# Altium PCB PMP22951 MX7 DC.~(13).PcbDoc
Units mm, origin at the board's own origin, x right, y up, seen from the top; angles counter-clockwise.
Board outline 96 x 43 mm, 6 copper layers (Top Layer, Layer 1, Layer 3, Layer 4, Layer 2, Bottom Layer), stack 1.671 mm thick; 4 components, 8 nets, 16 pads, 0 vias.
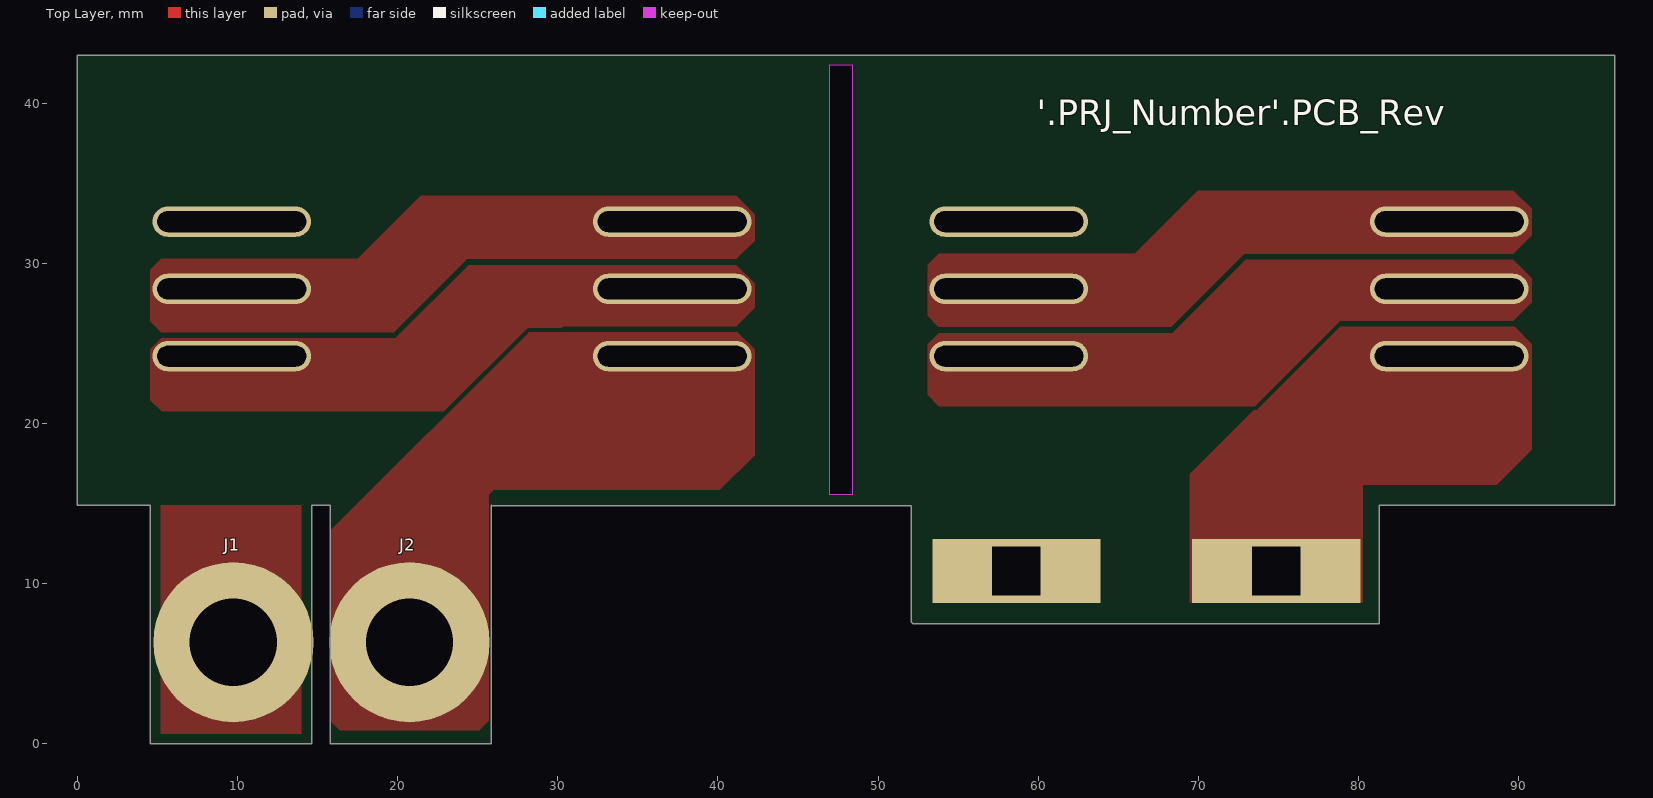
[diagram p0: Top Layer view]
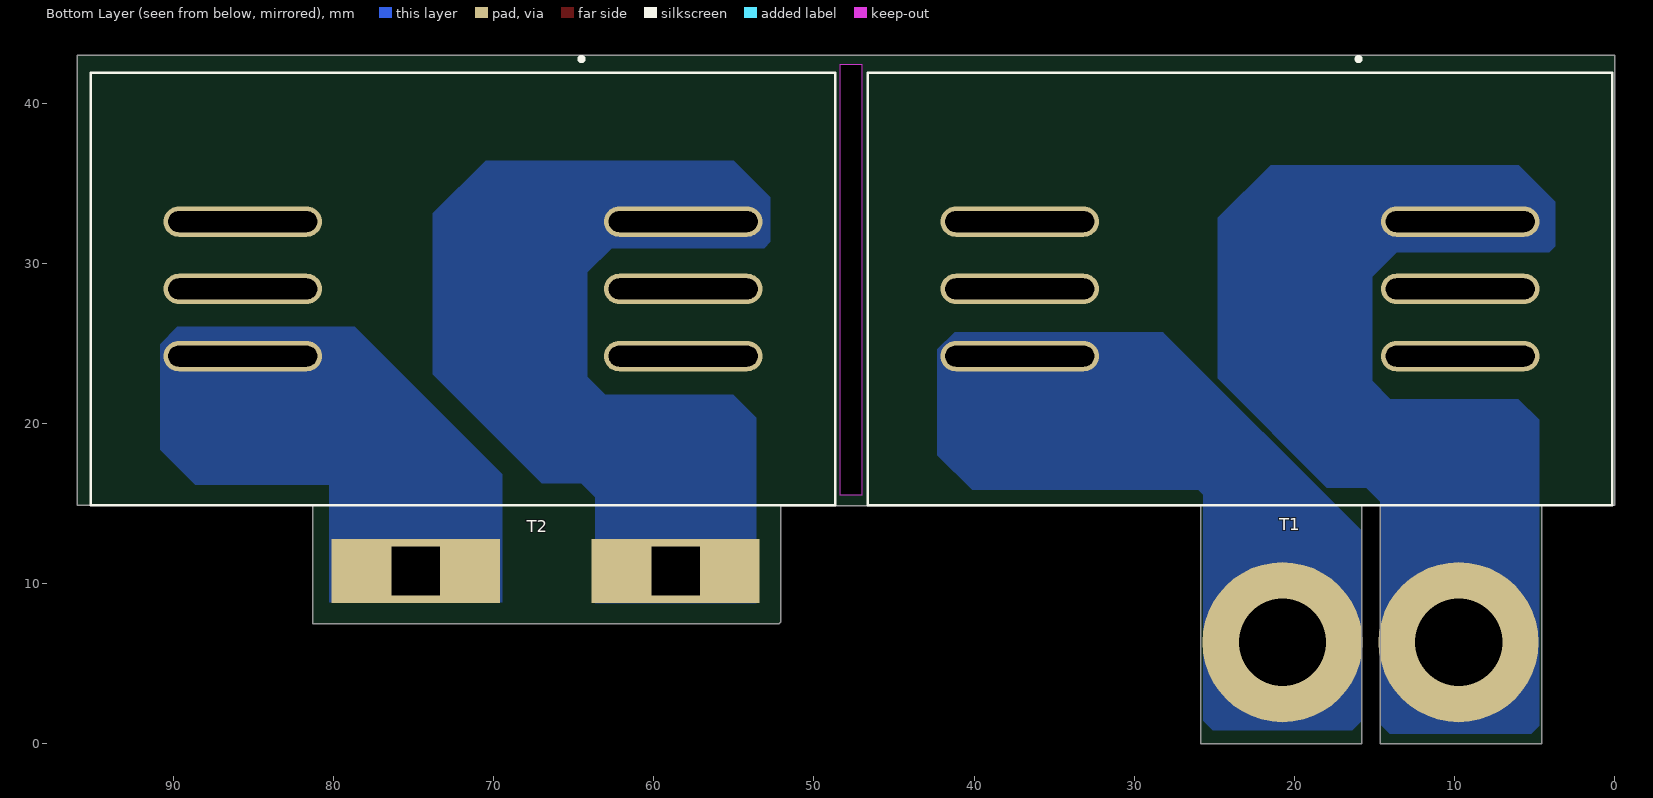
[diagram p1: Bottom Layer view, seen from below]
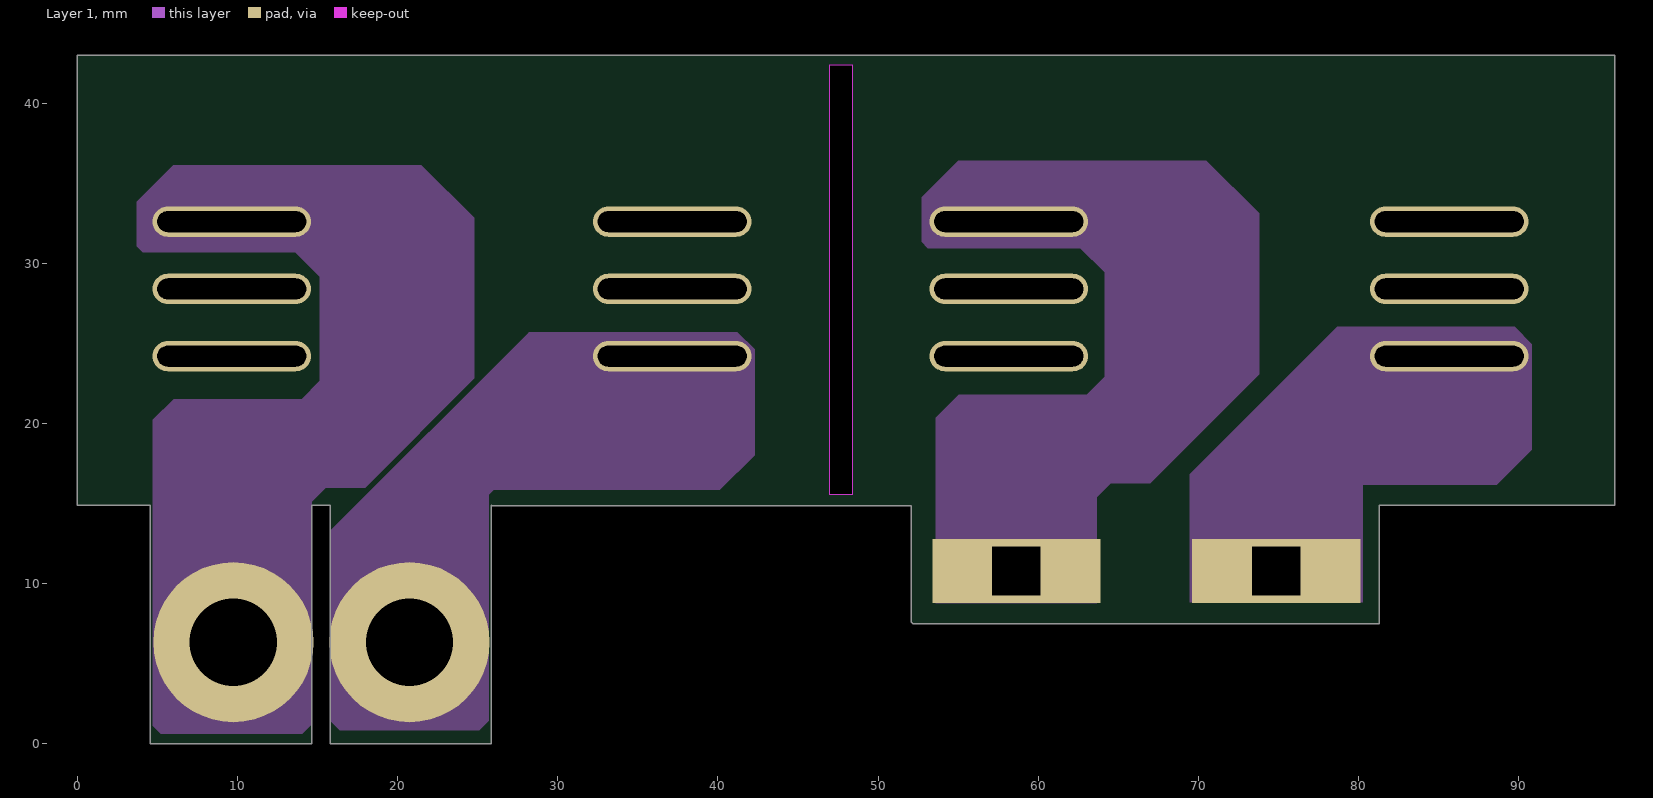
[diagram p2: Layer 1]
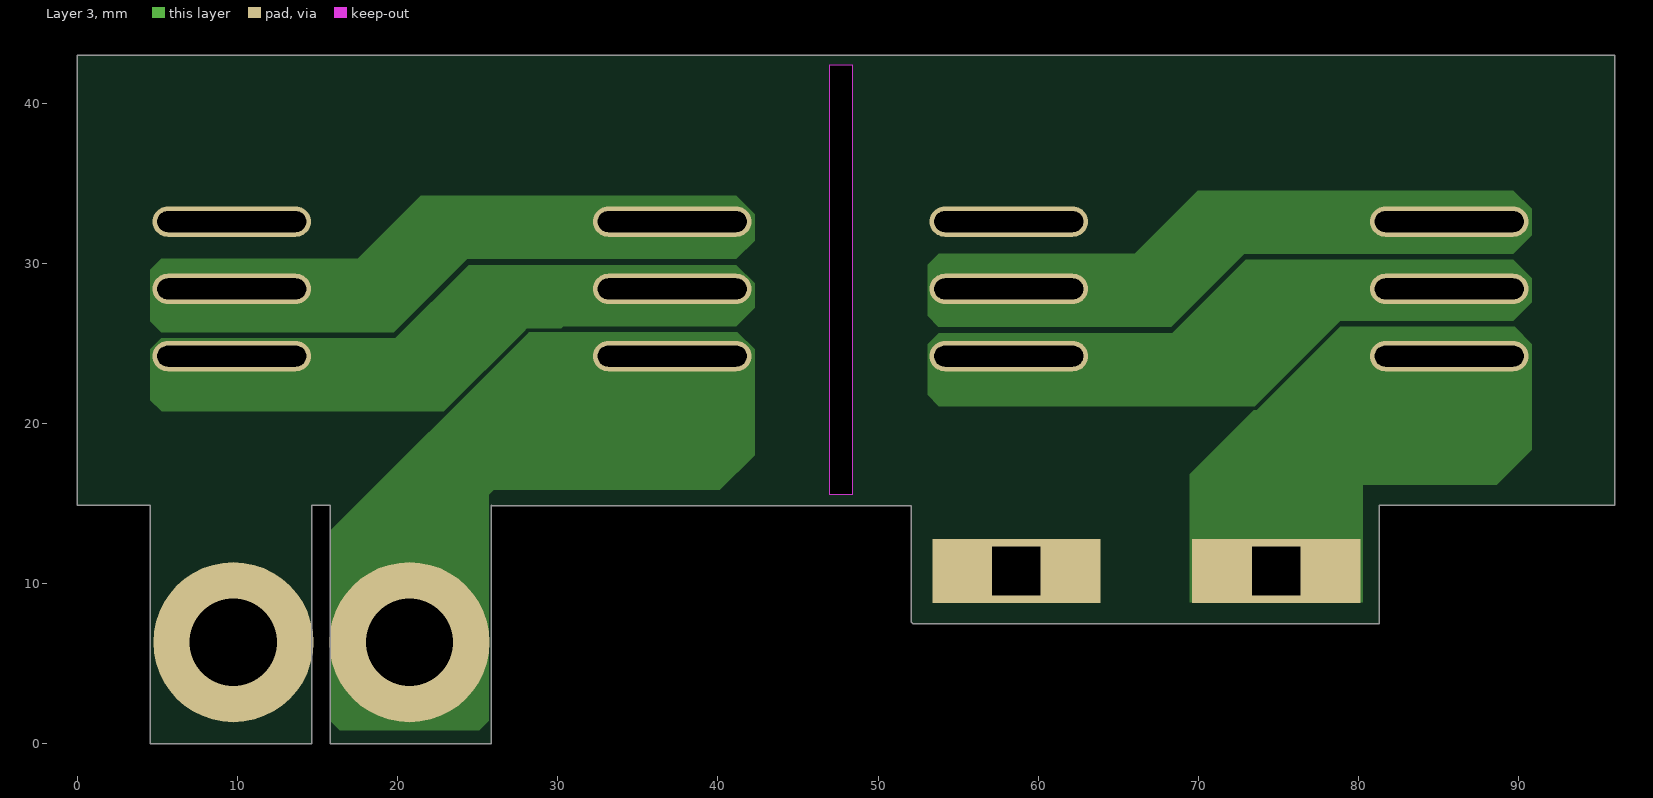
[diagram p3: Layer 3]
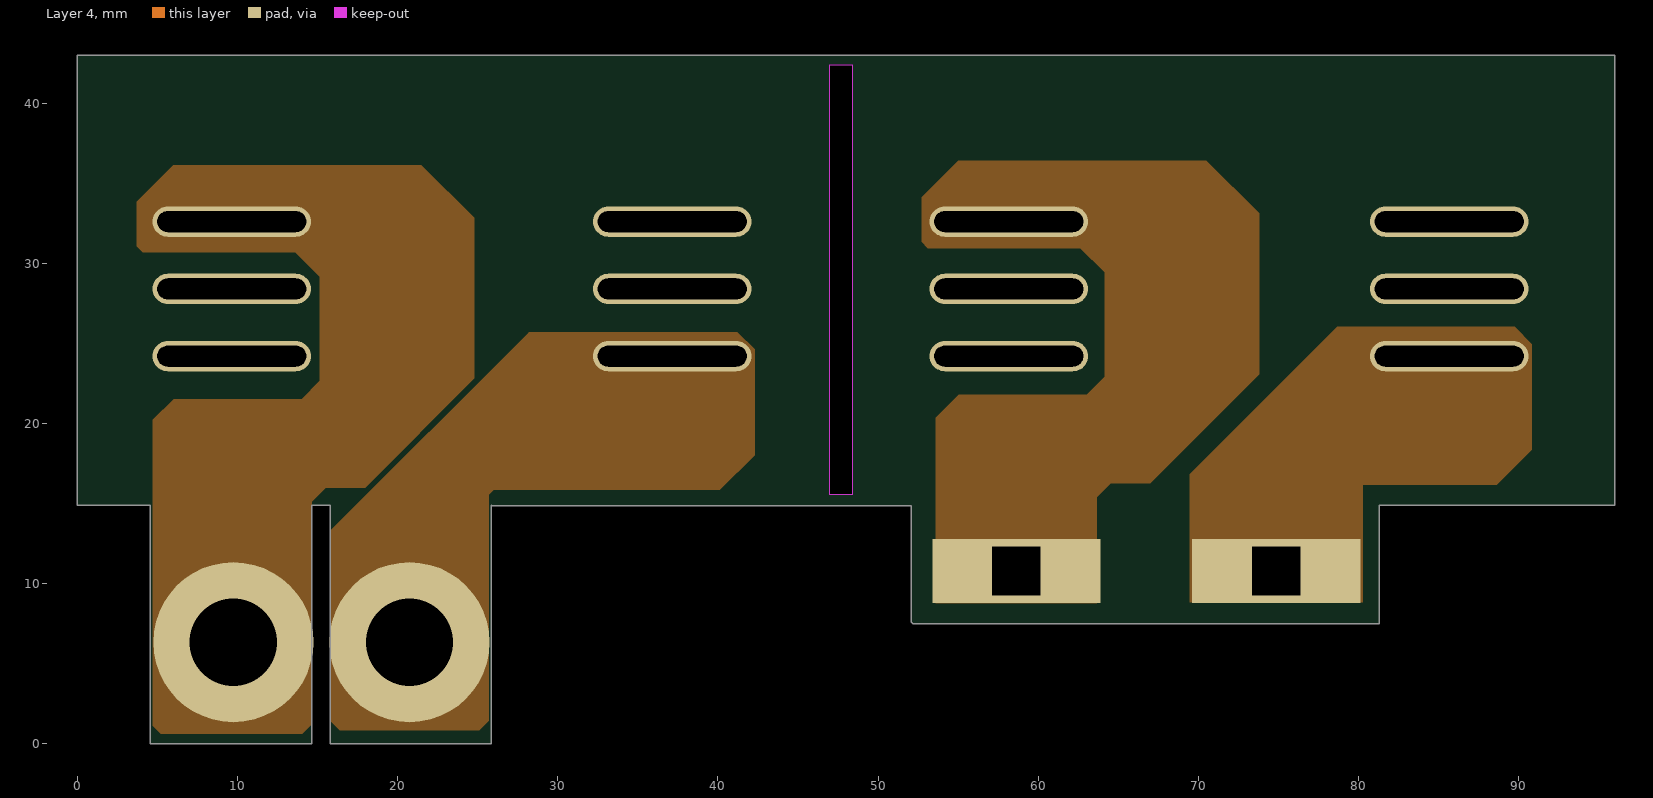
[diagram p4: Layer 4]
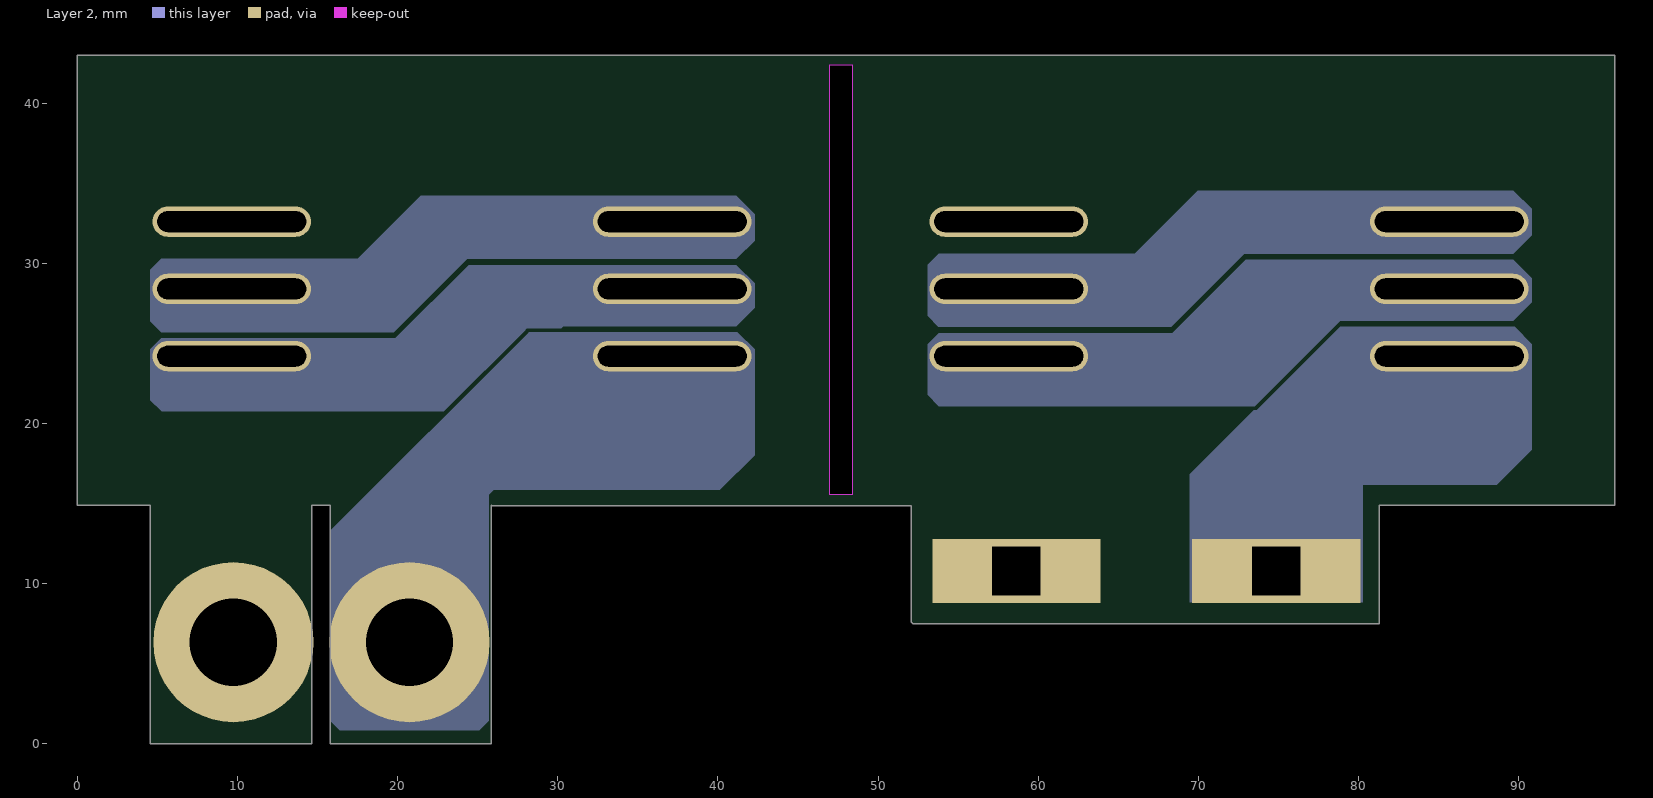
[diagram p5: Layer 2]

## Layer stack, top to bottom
Top Solder: solder mask 0.0102, Solder Resist, Dk 3.5
Top Layer: signal copper 0.0711
Dielectric 1: prepreg 0.1778, PP-006, Dk 4.1
Layer 1: signal copper 0.0711
Dielectric 5: core 0.3556, Core-009, Dk 4.5
Layer 3: signal copper 0.0711
Dielectric1: core 0.1778, FR-4 High Tg, Dk 4.8
Layer 4: signal copper 0.0711
Dielectric 6: core 0.3556, Core-009, Dk 4.5
Layer 2: signal copper 0.0711
Dielectric 2: prepreg 0.1778, PP-006, Dk 4.1
Bottom Layer: signal copper 0.0711
Bottom Solder: solder mask 0.0102, Solder Resist, Dk 3.5

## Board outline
4.572,0 4.572,14.91 0,14.91 0,43 96,43 96,14.893 81.28,14.893 81.28,7.493 52.197,7.493 52.07,7.62 52.07,14.859 25.901,14.859 25.85,14.91 25.85,0 15.8,0 15.8,14.91 14.629,14.91 14.629,0
cut-out: 46.99,42.418 48.387,42.418 48.387,15.555 46.99,15.555

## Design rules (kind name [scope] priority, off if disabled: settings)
AcuteAngle [All] p1: minimum=4.50000000000000E+0001 checktracksonly=FALSE
AssemblyTestPointUsage [All] p1: valid=2
BoardOutlineClearance BoardOutlineClearance_MountingHoles [OnCopper and InComponentClass('Mounting Holes')] p1: gap=1 ignorepadtopadclearanceinfootprint=FALSE
BoardOutlineClearance BoardOutlineClearance_Poly [OnCopper and IsPoly] p2: gap=0.635 ignorepadtopadclearanceinfootprint=FALSE
BoardOutlineClearance [OnCopper and Not InComponentClass('Logo') and not InComponentClass('FiducialMark') and not InRegion(1000,500,4000,800) and not InPoly] p3: gap=1.016 ignorepadtopadclearanceinfootprint=FALSE
Clearance Clearance_Keepouts [((IsTrack Or IsArc) And Not InPoly) And IsFree and IsKeepOut vs ((IsTrack Or IsArc) And Not InPoly) And IsFree and IsKeepOut] p1: gap=0 ignorepadtopadclearanceinfootprint=FALSE
Clearance Clearance_Poly [InPolygon] p2: gap=0.254 ignorepadtopadclearanceinfootprint=TRUE
Clearance Clearance_FiducialMark [IsKeepOut and InComponentClass('FiducialMark') vs IsPad and InComponentClass('FiducialMark')] p3: gap=0 ignorepadtopadclearanceinfootprint=FALSE
Clearance [All] p4: gap=0.2 ignorepadtopadclearanceinfootprint=TRUE
ComponentClearance ComponentClearance_MountingHoles_FiducialMarks [InComponentClass('Mounting Holes') vs InComponentClass('FiducialMark')] p1: gap=1.27 collisioncheckmode=3 verticalgap=0.254 showdistances=FALSE
ComponentClearance ComponentClearance_Shunt [InComponentClass('Header') vs InComponentClass('Shunt')] p2: gap=0 collisioncheckmode=3 verticalgap=0 showdistances=FALSE
ComponentClearance ComponentClearance_Logo [InComponentClass('Logo')] p3: gap=0.762 collisioncheckmode=3 verticalgap=0.254 showdistances=FALSE
ComponentClearance ComponentClearance_ScrewToNut [(HasFootprint('NY PMS 440 0025 PH')) vs (HasFootprint('Keystone_1902C'))] p4: gap=0.127 collisioncheckmode=3 verticalgap=0.254 showdistances=FALSE
ComponentClearance ComponentClearance_MountingHoles [InComponentClass('Mounting Holes')] p5: gap=2.54 collisioncheckmode=3 verticalgap=2540 showdistances=FALSE
ComponentClearance ComponentClearance_SmallPassives [HasFootprint('0201*') or HasFootprint('0402*') or HasFootprint('0508') or HasFootprint('0603*') or HasFootprint('0612') or HasFootprint('0805*') or HasFootprint('0815*') or HasFootprint('0830*') or HasFootprint('1206*') or HasFootprint('1210*') or HasFootprint('1808*') or HasFootprint('1812*') or HasFootprint('1825*') or HasFootprint('2010*') or HasFootprint('2220*') or HasFootprint('2225*') or HasFootprint('2512*') or HasFootprint('2728*') or HasFootprint('3518*') vs HasFootprint('0201*') or HasFootprint('0402*') or HasFootprint('0508') or HasFootprint('0603*') or HasFootprint('0612') or HasFootprint('0805*') or HasFootprint('0815*') or HasFootprint('0830*') or HasFootprint('1206*') or HasFootprint('1210*') or HasFootprint('1808*') or HasFootprint('1812*') or HasFootprint('1825*') or HasFootprint('2010*') or HasFootprint('2220*') or HasFootprint('2225*') or HasFootprint('2512*') or HasFootprint('2728*') or HasFootprint('3518*')] p6: gap=0.38 collisioncheckmode=3 verticalgap=0.254 showdistances=FALSE
ComponentClearance ComponentClearance_THtoSMT [IsThruComponent vs IsSMTComponent] p7: gap=0.762 collisioncheckmode=3 verticalgap=0.762 showdistances=FALSE
ComponentClearance ComponentClearance_THtoTH [IsThruComponent vs IsThruComponent] p8: gap=0.508 collisioncheckmode=3 verticalgap=0.762 showdistances=FALSE
ComponentClearance [All] p9: gap=0.508 collisioncheckmode=3 verticalgap=0.254 showdistances=FALSE
DiffPairsRouting [All] p1: maxlimit=2.54 minlimit=0.254 mostfreqgap=0.254 toplayer_minwidth=0.381 toplayer_maxwidth=0.381 toplayer_prefwidth=0.381 midlayer1_minwidth=0.381 midlayer1_maxwidth=0.381 midlayer1_prefwidth=0.381 midlayer2_minwidth=0.381 midlayer2_maxwidth=0.381 midlayer2_prefwidth=0.381 midlayer3_minwidth=0.381 midlayer3_maxwidth=0.381 midlayer3_prefwidth=0.381 midlayer4_minwidth=0.381 midlayer4_maxwidth=0.381 midlayer4_prefwidth=0.381 bottomlayer_minwidth=0.381 bottomlayer_maxwidth=0.381 bottomlayer_prefwidth=0.381 maxuncoupledlength=25.4
FabricationTestPointUsage TestPointUsage [All] p1: valid=2 allowmultiple=FALSE
FabricationTestpoint Testpoint [All] p1: side=3 testpointundercomponent=TRUE minsize=1.016 maxsize=2.54 preferedsize=1.524 minholesize=0 maxholesize=1.016 preferedholesize=0.813 testpointgrid=0.025 allowsidetop=TRUE allowsidebottom=TRUE usegrid=TRUE gridtolerance=0
FanoutControl Fanout_LCC [IsLCC] p1: bgadir=Out bgaviamode=Centered fanoutstyle=Auto fanoutdirection=Alternating viagrid=0.025 // Fanout_LCC (Default Rule)
FanoutControl Fanout_BGA [IsBGA] p2: bgadir=Out bgaviamode=Centered fanoutstyle=Auto fanoutdirection=Alternating viagrid=0.025 // Fanout_BGA (Default Rule)
FanoutControl Fanout_Default [All] p4: bgadir=Out bgaviamode=Centered fanoutstyle=Auto fanoutdirection=Alternating viagrid=0.025 // Fanout_Default (Default Rule)
FanoutControl Fanout_Small [(CompPinCount < 5)] p5: bgadir=Out bgaviamode=Centered fanoutstyle=Auto fanoutdirection=OutThenIn viagrid=0.025 // Fanout_Small (Default Rule)
HoleSize [All] p1: absolutevalues=TRUE maxlimit=6.375 minlimit=0.2 maxpercent=80.000 minpercent=20.000
MinimumAnnularRing MinimumAnnularRing_ThermalPadVias [IsVia and InAnyComponent] p1: minimumring=0.15
MinimumAnnularRing [All] p2: minimumring=0.2
MinimumSolderMaskSliver MinimumSolderMaskSliver_Logo [InComponentClass('Logo') vs InComponentClass('Logo')] p1: minsoldermaskwidth=0.018
MinimumSolderMaskSliver [All] p2: minsoldermaskwidth=0.1
PlaneConnect [All] p1: planeconnectstyle=Direct reliefexpansion=0.254 reliefentries=4 reliefconductorwidth=0.254 reliefairgap=0.254
PolygonConnect [All] p1: connectstyle=Direct reliefconductorwidth=0.254 reliefentries=4 polygonreliefangle="90 Angle" airgapwidth=0.254
RoutingLayers [All] p1: top layer_v5=TRUE mid layer 1_v5=FALSE mid layer 2_v5=FALSE mid layer 3_v5=FALSE mid layer 4_v5=FALSE bottom layer_v5=TRUE
RoutingVias ThermalPadVias [IsVia and InAnyComponent] p1: holewidth=0.2 width=0.5 viastyle="Through Hole" minholewidth=0.2 minwidth=0.5 maxholewidth=0.33 maxwidth=0.6
RoutingVias [All] p2: holewidth=0.406 width=0.864 viastyle="Through Hole" minholewidth=0.2 minwidth=0.61 maxholewidth=1.016 maxwidth=1.651
SilkToBoardRegionClearance [Not ((IsComment or IsDesignator) And (Hide <> 'False')) and not InRegion(1000,500,4000,800)] p1:
SilkToSilkClearance SilkToSilkClearance_Pb-FreeLogo [(HasFootprint('Pb-Free_Overlay_Medium') OR HasFootprint('Pb-Free_Overlay_Small')) vs (HasFootprint('Pb-Free_Overlay_Medium') OR HasFootprint('Pb-Free_Overlay_Small'))] p1: silktosilkclearance=0
SilkToSilkClearance [All] p2: silktosilkclearance=0.1
SilkToSolderMaskClearance SilkToComponentPadClearance [(IsPad or IsFill or IsRegion) and InAnycomponent] p1: minsilkscreentomaskgap=0.127 clearancetoexposedcopper=TRUE
SilkToSolderMaskClearance "Silk to Solder Mask Opening" [All] p2: minsilkscreentomaskgap=0.1 clearancetoexposedcopper=FALSE
SolderMaskExpansion [All] p1: expansion=0.05 istentingtop=FALSE
UnRoutedNet [All] p1: checkbadconnections=TRUE
Width [All] p1: maxlimit=2.54 minlimit=0.152 preferedwidth=0.254 checkconnectedcopper=TRUE
13 further rules are at their usual default settings.

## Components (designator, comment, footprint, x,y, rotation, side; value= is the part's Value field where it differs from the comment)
J1 "575-4" Keystone_575-4 9.75,6.35 r0 top
J2 "575-4" Keystone_575-4 20.75,6.35 r0 top
T1 "PAT6289NL MX7" "FP-PAT6289NL MX7_PTH8_46MM5_27MM0-MFG" 23.402,28.41 r0 bottom
T2 "PAT6289NL MX7" "FP-PAT6289NL MX7_PTH8_46MM5_27MM0-MFG" 71.916,28.41 r0 bottom

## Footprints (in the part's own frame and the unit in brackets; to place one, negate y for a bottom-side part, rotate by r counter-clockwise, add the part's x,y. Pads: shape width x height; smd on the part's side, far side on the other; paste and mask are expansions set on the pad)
"FP-PAT6289NL MX7_PTH8_46MM5_27MM0-MFG" [mm]
  rrect100% 9.9x1.9 hole 1.3 slot 9.3 at 0 deg paste-1000 mask+0: 3(13.75,4.2) 4(13.75,0) 5(13.75,-4.2) 6(-13.75,-4.2) 7(-13.75,0) 8(-13.75,4.2)
  silkscreen extent -23.25,-14.47 23.25,13.5, body extent -23.25,-53.5 23.25,63.5, height 32.5
Keystone_575-4 [mm] "Banana Jack"
  round 10 hole 5.45: 1(0,0)
  body extent -3.95,-3.95 3.92,3.93, height 2.36

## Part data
J1 J2: library part CMP-0055165-2, "Standard Banana Jack, Uninsulated, 5.5mm", Manufacturer=Keystone, Supplier Part Number 1=36-575-4-ND
T1 T2: library part CMP-0120260-1, "Transformer PSFB 2.7kW EW45 TH", Frequency_Fixed=140-200kHz, Manufacturer=Pulse, Operating Temperature Range="-40°C to +125°C", Voltage_Isolation_Vrms=3kV

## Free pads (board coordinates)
  rect 10.5x4 hole 3 square: 2(58.64,10.795) 2(74.864,10.795)

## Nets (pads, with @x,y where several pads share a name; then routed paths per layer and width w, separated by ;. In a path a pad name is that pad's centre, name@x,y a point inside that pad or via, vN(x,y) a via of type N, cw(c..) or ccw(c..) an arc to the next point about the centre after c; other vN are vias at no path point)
NetJ1_1: J1.1 T1.6
NetJ2_1: J2.1 T1.3
NetT1_4: T1.4 T1.8
NetT1_5: T1.5 T1.7
NetT2_4: T2.4 T2.8
NetT2_5: T2.5 T2.7
SW3: pad.2@58.64,10.795 T2.6
SW4: pad.2@74.864,10.795 T2.3

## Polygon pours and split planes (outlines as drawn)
NetJ1_1 on Top Layer "TOP_LAYER_NETJ1_1_P042" (solid, pour order 42): 4.572,14.91 14.629,14.91 14.629,0 4.572,0
NetJ2_1 on Top Layer "SWNODE4" (solid, remove dead copper, pour order 0): 28.2,25.705 28.15,25.655 15.8,13.305 15.8,1.455 16.4,0.855 25.1,0.855 25.7,1.455 25.7,15.555 26,15.855 40.114,15.855 42.291,18.031 42.291,24.638 41.224,25.705
NetT2_5 on Top Layer "SWNODE4" (solid, remove dead copper, pour order 20): 53.779,30.607 53.089,29.917 53.089,26.721 53.775,26.035 68.292,26.035 72.864,30.607 89.662,30.607 90.808,31.753 90.808,33.398 89.662,34.544 69.977,34.544 66.04,30.607
NetT2_4 on Top Layer "SWNODE3" (solid, remove dead copper, pour order 19): 53.796,21.082 53.089,21.789 53.089,24.964 53.779,25.654 68.384,25.654 72.956,30.226 89.662,30.226 90.808,29.08 90.808,27.562 89.662,26.416 78.862,26.416 73.528,21.082
SW4 on Top Layer "SWNODE4" (solid, remove dead copper, pour order 18): 78.672,26.031 69.469,16.828 69.469,8.831 80.264,8.831 80.264,16.181 88.631,16.181 90.808,18.357 90.808,24.964 89.741,26.031
NetT1_5 on Top Layer "SWNODE4" (solid, remove dead copper, pour order 2): 5.262,30.281 4.572,29.591 4.572,26.395 5.258,25.709 19.775,25.709 24.347,30.281 41.145,30.281 42.291,31.427 42.291,33.072 41.145,34.218 21.46,34.218 17.523,30.281
NetT1_4 on Top Layer "SWNODE3" (solid, remove dead copper, pour order 1): 5.279,20.756 4.572,21.463 4.572,24.638 5.262,25.328 19.867,25.328 24.439,29.9 41.145,29.9 42.291,28.754 42.291,27.236 41.145,26.09 30.345,26.09 25.011,20.756
NetJ2_1 on Layer 1 "SWNODE4" (solid, remove dead copper, pour order 11): 28.2,25.705 28.15,25.655 15.8,13.305 15.8,1.455 16.4,0.855 25.1,0.855 25.7,1.455 25.7,15.555 26,15.855 40.114,15.855 42.291,18.031 42.291,24.638 41.224,25.705
SW4 on Layer 1 "SWNODE4" (solid, remove dead copper, pour order 33): 78.672,26.031 69.469,16.828 69.469,8.831 80.264,8.831 80.264,16.181 88.631,16.181 90.808,18.357 90.808,24.964 89.741,26.031
SW3 on Layer 1 "SWNODE3" (solid, remove dead copper, pour order 21): 73.806,23.091 66.993,16.278 64.516,16.278 63.64,15.402 63.64,8.781 53.594,8.781 53.594,20.356 55.04,21.802 63.019,21.802 64.156,22.939 64.156,29.433 62.63,30.959 53.105,30.959 52.724,31.34 52.724,34.134 55.01,36.42 70.504,36.42 73.806,33.118
NetJ1_1 on Layer 1 "SWNODE3" (solid, remove dead copper, pour order 3): 24.795,22.815 17.982,16.002 15.505,16.002 14.629,15.126 14.629,1.226 14.029,0.626 5.229,0.626 4.729,1.126 4.729,20.226 6.029,21.526 14.008,21.526 15.145,22.663 15.145,29.157 13.619,30.683 4.094,30.683 3.713,31.064 3.713,33.858 5.999,36.144 21.493,36.144 24.795,32.842
NetJ2_1 on Layer 3 "SWNODE4" (solid, remove dead copper, pour order 4): 28.2,25.705 28.15,25.655 15.8,13.305 15.8,1.455 16.4,0.855 25.1,0.855 25.7,1.455 25.7,15.555 26,15.855 40.114,15.855 42.291,18.031 42.291,24.638 41.224,25.705
SW4 on Layer 3 "SWNODE4" (solid, remove dead copper, pour order 34): 78.672,26.031 69.469,16.828 69.469,8.831 80.264,8.831 80.264,16.181 88.631,16.181 90.808,18.357 90.808,24.964 89.741,26.031
NetT2_5 on Layer 3 "SWNODE4" (solid, remove dead copper, pour order 25): 53.779,30.607 53.089,29.917 53.089,26.721 53.775,26.035 68.292,26.035 72.864,30.607 89.662,30.607 90.808,31.753 90.808,33.398 89.662,34.544 69.977,34.544 66.04,30.607
NetT2_4 on Layer 3 "SWNODE3" (solid, remove dead copper, pour order 24): 53.796,21.082 53.089,21.789 53.089,24.964 53.779,25.654 68.384,25.654 72.956,30.226 89.662,30.226 90.808,29.08 90.808,27.562 89.662,26.416 78.862,26.416 73.528,21.082
NetT1_5 on Layer 3 "SWNODE4" (solid, remove dead copper, pour order 6): 5.262,30.281 4.572,29.591 4.572,26.395 5.258,25.709 19.775,25.709 24.347,30.281 41.145,30.281 42.291,31.427 42.291,33.072 41.145,34.218 21.46,34.218 17.523,30.281
NetT1_4 on Layer 3 "SWNODE3" (solid, remove dead copper, pour order 5): 5.279,20.756 4.572,21.463 4.572,24.638 5.262,25.328 19.867,25.328 24.439,29.9 41.145,29.9 42.291,28.754 42.291,27.236 41.145,26.09 30.345,26.09 25.011,20.756
SW3 on Layer 4 "SWNODE3" (solid, remove dead copper, pour order 38): 73.806,23.091 66.993,16.278 64.516,16.278 63.64,15.402 63.64,8.781 53.594,8.781 53.594,20.356 55.04,21.802 63.019,21.802 64.156,22.939 64.156,29.433 62.63,30.959 53.105,30.959 52.724,31.34 52.724,34.134 55.01,36.42 70.504,36.42 73.806,33.118
SW4 on Layer 4 "SWNODE4" (solid, remove dead copper, pour order 35): 78.672,26.031 69.469,16.828 69.469,8.831 80.264,8.831 80.264,16.181 88.631,16.181 90.808,18.357 90.808,24.964 89.741,26.031
NetJ2_1 on Layer 4 "SWNODE4" (solid, remove dead copper, pour order 12): 28.2,25.705 28.15,25.655 15.8,13.305 15.8,1.455 16.4,0.855 25.1,0.855 25.7,1.455 25.7,15.555 26,15.855 40.114,15.855 42.291,18.031 42.291,24.638 41.224,25.705
NetJ1_1 on Layer 4 "SWNODE3" (solid, remove dead copper, pour order 7): 24.795,22.815 17.982,16.002 15.505,16.002 14.629,15.126 14.629,1.226 14.029,0.626 5.229,0.626 4.729,1.126 4.729,20.226 6.029,21.526 14.008,21.526 15.145,22.663 15.145,29.157 13.619,30.683 4.094,30.683 3.713,31.064 3.713,33.858 5.999,36.144 21.493,36.144 24.795,32.842
SW4 on Layer 2 "SWNODE4" (solid, remove dead copper, pour order 36): 78.672,26.031 69.469,16.828 69.469,8.831 80.264,8.831 80.264,16.181 88.631,16.181 90.808,18.357 90.808,24.964 89.741,26.031
NetT2_5 on Layer 2 "SWNODE4" (solid, remove dead copper, pour order 28): 53.779,30.607 53.089,29.917 53.089,26.721 53.775,26.035 68.292,26.035 72.864,30.607 89.662,30.607 90.808,31.753 90.808,33.398 89.662,34.544 69.977,34.544 66.04,30.607
NetT2_4 on Layer 2 "SWNODE3" (solid, remove dead copper, pour order 27): 53.796,21.082 53.089,21.789 53.089,24.964 53.779,25.654 68.384,25.654 72.956,30.226 89.662,30.226 90.808,29.08 90.808,27.562 89.662,26.416 78.862,26.416 73.528,21.082
NetT1_5 on Layer 2 "SWNODE4" (solid, remove dead copper, pour order 10): 5.262,30.281 4.572,29.591 4.572,26.395 5.258,25.709 19.775,25.709 24.347,30.281 41.145,30.281 42.291,31.427 42.291,33.072 41.145,34.218 21.46,34.218 17.523,30.281
NetT1_4 on Layer 2 "SWNODE3" (solid, remove dead copper, pour order 9): 5.279,20.756 4.572,21.463 4.572,24.638 5.262,25.328 19.867,25.328 24.439,29.9 41.145,29.9 42.291,28.754 42.291,27.236 41.145,26.09 30.345,26.09 25.011,20.756
NetJ2_1 on Layer 2 "SWNODE4" (solid, remove dead copper, pour order 8): 28.2,25.705 28.15,25.655 15.8,13.305 15.8,1.455 16.4,0.855 25.1,0.855 25.7,1.455 25.7,15.555 26,15.855 40.114,15.855 42.291,18.031 42.291,24.638 41.224,25.705
no net on Top Solder "NONET_L-01_P-001" (solid): 15.8,14.91 15.8,0 25.85,0 25.875,0.025 25.875,14.884
no net on Top Solder "NONET_L-01_P-001" (solid): 4.572,14.91 14.629,14.91 14.629,0 4.572,0
SW3 on Bottom Layer "SWNODE3" (solid, remove dead copper, pour order 39): 73.806,23.091 66.993,16.278 64.516,16.278 63.64,15.402 63.64,8.781 53.594,8.781 53.594,20.356 55.04,21.802 63.019,21.802 64.156,22.939 64.156,29.433 62.63,30.959 53.105,30.959 52.724,31.34 52.724,34.134 55.01,36.42 70.504,36.42 73.806,33.118
SW4 on Bottom Layer "SWNODE4" (solid, remove dead copper, pour order 37): 78.672,26.031 69.469,16.828 69.469,8.831 80.264,8.831 80.264,16.181 88.631,16.181 90.808,18.357 90.808,24.964 89.741,26.031
NetJ2_1 on Bottom Layer "SWNODE4" (solid, remove dead copper, pour order 14): 28.2,25.705 28.15,25.655 15.8,13.305 15.8,1.455 16.4,0.855 25.1,0.855 25.7,1.455 25.7,15.555 26,15.855 40.114,15.855 42.291,18.031 42.291,24.638 41.224,25.705
NetJ1_1 on Bottom Layer "SWNODE3" (solid, remove dead copper, pour order 13): 24.795,22.815 17.982,16.002 15.505,16.002 14.629,15.126 14.629,1.226 14.029,0.626 5.229,0.626 4.729,1.126 4.729,20.226 6.029,21.526 14.008,21.526 15.145,22.663 15.145,29.157 13.619,30.683 4.094,30.683 3.713,31.064 3.713,33.858 5.999,36.144 21.493,36.144 24.795,32.842
no net on Bottom Solder "NONET_L-01_P-001" (solid): 15.8,14.91 15.8,0 25.85,0 25.875,0.025 25.875,14.884
no net on Bottom Solder "NONET_L-01_P-001" (solid): 4.572,14.91 14.629,14.91 14.629,0 4.572,0

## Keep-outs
Keep-Out Layer:
  region: 46.99,42.418 48.387,42.418 48.387,15.555 46.99,15.555
  text ".Layer_Name" at 14.656,-21.806 h1.52

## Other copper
Top Layer:
  text ".Layer_Name" at 14.656,-21.806 h1.52
Bottom Layer:
  text ".Layer_Name" at 14.656,-21.806 h1.52

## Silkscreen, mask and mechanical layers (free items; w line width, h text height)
Top Overlay:
  text "'.PRJ_Number'.PCB_Rev" at 59.909,38.1 h2.75
  text ".Layer_Name" at 14.656,-21.806 h1.52
Bottom Overlay:
  text ".Layer_Name" at 14.656,-21.806 h1.52
Top Paste:
  text ".Layer_Name" at 14.656,-21.806 h1.52
Bottom Paste:
  text ".Layer_Name" at 14.656,-21.806 h1.52
Top Solder:
  text ".Layer_Name" at 14.656,-21.806 h1.52
  text ".Layer_Name" at 14.656,-21.806 h1.52
Bottom Solder:
  text ".Layer_Name" at 14.656,-21.806 h1.52
Drill Guide:
  text ".Layer_Name" at 14.656,-21.806 h1.52
M1 Board Outline:
  lines w0.254: 0,14.91 4.572,14.91 4.572,0 14.629,0 14.629,14.91 15.8,14.91 15.8,0 25.85,0 25.85,14.91 25.901,14.859 52.07,14.859 52.07,7.62 52.197,7.493 81.28,7.493 81.28,14.893 96,14.893 96,43 0,43 0,14.91 ; 46.99,15.555 46.99,42.418 48.387,42.418 48.387,15.555 46.99,15.555
  text ".Layer_Name" at 14.656,-21.806 h1.52
M2 Board Dimensions:
  rectangle: 0,-6.985 3.175,-3.81
  rectangle: 3.175,-10.16 12.7,-6.985
  lines w0.178: 0,-6.985 25.4,-6.985 ; 3.175,-10.16 3.175,-3.81 ; 6.35,-10.16 6.35,-3.81 ; 12.7,-10.16 12.7,-3.81 ; 19.05,-10.16 19.05,-3.81 ; 0,-10.16 25.4,-10.16 25.4,-3.81 0,-3.81 0,-10.16
  text ".Layer_Name" at 14.656,-21.806 h1.52
M3 3D STEP Top:
  text ".Layer_Name" at 14.656,-21.806 h1.52
M4 3D STEP Bottom:
  text ".Layer_Name" at 14.656,-21.806 h1.52
M5 Assembly Top:
  lines w0.254: -7.417,-23.626 160.223,-23.626 ; -7.417,-18.462 160.274,-18.462 ; -7.417,-13.297 -7.417,-28.791 94.31,-28.791 160.274,-28.791 160.274,-13.297 -7.404,-13.297 -7.404,-28.791 32.614,-28.791 ; 55.194,-28.791 55.194,-13.297 ; 87.376,-18.462 87.376,-13.297 ; 108.712,-18.462 108.712,-13.297 ; 124.511,-28.956 124.511,-23.804
  text "COMPONENTS MARKED 'DNP' SHOULD NOT BE POPULATED." at 29.299,-8.09 h1.52
  text "ASSEMBLY VARIANT:" at 29.286,-11.024 h1.52
  text ".VariantName" at 55.601,-11.024 h1.52
  text "PCB VIEWED FROM TOP SIDE" at -5.804,-16.654 h1.52
  text "BOARD #:" at 57.099,-16.654 h1.52
  text ".PRJ_Number" at 70.955,-16.654 h1.52
  text "REV:" at 92.405,-16.654 h1.52
  text ".PCB_Rev" at 99.809,-16.654 h1.52
  text "SVN REV:" at 113.69,-16.654 h1.52
  text ".VersionControl_RevNumber" at 126.543,-16.654 h1.52
  text "TID #:" at 57.099,-21.819 h1.52
  text ".TID" at 70.955,-21.819 h1.52
  text "PLOT NAME =" at -5.804,-27.034 h1.52
  text ".plot_File_Name" at 14.656,-27.034 h1.52
  text "GENERATED    :" at 57.15,-27.034 h1.52
  text ".Print_Date" at 79.235,-27.034 h1.52
  text ".Print_Time" at 97.752,-27.034 h1.52
  text "TEXAS INSTRUMENTS" at 129.87,-27.034 h1.52
M6 Assembly Bottom:
  lines w0.254: -7.429,-18.474 160.261,-18.474 ; -7.379,-23.639 160.261,-23.639 ; 28.334,-28.969 28.334,-23.817 ; 44.133,-18.474 44.133,-13.31 ; 65.468,-18.474 65.468,-13.31 ; 97.65,-28.804 97.65,-13.31 ; 120.231,-28.804 160.249,-28.804 160.249,-13.31 -7.429,-13.31 -7.429,-28.804 58.534,-28.804 160.261,-28.804 160.261,-13.31
  text "COMPONENTS MARKED 'DNP' SHOULD NOT BE POPULATED." at 154.991,-8.077 h1.52
  text ".VariantName" at 128.473,-11.024 h1.52
  text "ASSEMBLY VARIANT:" at 154.864,-11.024 h1.52
  text ".VersionControl_RevNumber" at 26.302,-16.667 h1.52
  text "SVN REV:" at 39.154,-16.667 h1.52
  text ".PCB_Rev" at 53.035,-16.667 h1.52
  text "REV:" at 60.439,-16.667 h1.52
  text ".PRJ_Number" at 81.89,-16.667 h1.52
  text "BOARD #:" at 95.745,-16.667 h1.52
  text "PCB VIEWED FROM BOTTOM SIDE" at 158.648,-16.667 h1.52
  text ".TID" at 81.89,-21.831 h1.52
  text "TID #:" at 95.745,-21.831 h1.52
  text "TEXAS INSTRUMENTS" at 22.974,-27.047 h1.52
  text ".Print_Time" at 55.093,-27.047 h1.52
  text ".Print_Date" at 73.609,-27.047 h1.52
  text "GENERATED    :" at 95.694,-27.047 h1.52
  text ".plot_File_Name" at 138.189,-27.047 h1.52
  text "PLOT NAME =" at 158.648,-27.047 h1.52
M9 Title Sheet:
  drawing of 57 lines, arcs and shapes, not listed
  text "1" at 18.792,204.127 h1.78
  text "2" at 82.182,204.127 h1.78
  text "3" at 145.411,204.127 h1.78
  text "4" at 209.08,204.127 h1.78
  text "5" at 272.555,204.127 h1.78
  text "6" at 336.182,204.127 h1.78
  text "A" at -10.579,175.095 h1.78
  text "A" at 365.341,175.095 h1.78
  text "B" at -10.579,114.643 h1.78
  text "B" at 365.341,114.643 h1.78
  text "C" at -10.579,54.318 h1.78
  text "C" at 365.341,54.318 h1.78
  text "PROJECT TITLE:" at 288.125,7.048 h1.14
  text ".PRJ_Title" at 289.395,3.662 h1.78
  text "DESIGNED FOR:" at 288.125,-0.597 h1.14
  text ".PRJ_Customer" at 289.395,-4.153 h1.78
  text "D" at -10.579,-5.88 h1.78
  text "D" at 365.341,-5.88 h1.78
  text "FILE NAME:" at 288.125,-8.217 h1.14
  text ".PCB_File_Name_No_Path" at 289.395,-11.265 h1.78
  text "Texas Instruments (TI) and/or its licensors do not warrant the accuracy or completeness of this specification" at 161.9,-15.376 h1.14
  text "ENGINEER:" at 288.125,-15.583 h1.14
  text "LAYOUT BY:" at 326.352,-15.583 h1.14
  text "or any information contained therein. TI and/or its licensors do not warrant that this design will meet" at 160.757,-18.237 h1.14
  text ".PRJ_Engineer" at 289.395,-19.52 h1.78
  text ".PCB_Layout" at 327.635,-19.52 h1.78
  text "the specifications, will be suitable for your application or fit for any particular purpose, or will operate in" at 160.757,-21.099 h1.14
  text ".Layer_Name" at 14.656,-21.806 h1.52
  text "ALTIUM DESIGNER VERSION:" at 326.352,-23.457 h1.14
  text "an implementation. TI and/or its licensors do not warrant that the design is production worthy. You should" at 160.757,-23.961 h1.14
  text "completely validate and test your design implementation to confirm the system functionality for your application." at 161.9,-26.822 h1.14
  text ".print_Scale" at 289.395,-26.843 h1.78
  text ".Application_BuildNumber" at 327.635,-26.843 h1.78
  text "1" at 18.792,-32.093 h1.78
  text "2" at 82.182,-32.093 h1.78
  text "3" at 145.411,-32.093 h1.78
  text "4" at 209.08,-32.093 h1.78
  text "5" at 272.555,-32.093 h1.78
  text "6" at 336.182,-32.093 h1.78
M10 Fab Notes:
  drawing of 189 lines, arcs and shapes, not listed
  text "DESIGN INFORMATION" at 314.503,161.447 h1.52
  text "MIN. TRACK WIDTH:" at 298.131,158.091 h1.52
  text "8" at 325.976,158.091 h1.52
  text "MIL" at 329.907,158.091 h1.52
  text "7.874" at 321.75,155 h1.52
  text "MIN. CLEARANCE:" at 298.131,154.938 h1.52
  text "MIL" at 329.907,154.938 h1.52
  text "MIN. VIA PAD SIZE:" at 298.131,151.785 h1.52
  text "24" at 325.214,151.785 h1.52
  text "MIL" at 329.907,151.785 h1.52
  text "0.05mm (2MIL)" at 315.784,148.486 h1.52
  text "MINIMUM ANNULAR RING" at 289.769,148.277 h1.52
  text "EXTERNAL" at 333.768,148.277 h1.52
  text "PER" at 294.849,145.48 h1.52
  text "IPC-D-275 CLASS 2 LEVEL C" at 300.437,145.48 h1.52
  text "MIL, HOLES" at 338.238,142.928 h1.52
  text "+/-" at 328.27,142.709 h1.52
  text "+/-" at 349.961,142.709 h1.52
  text "REGISTRATION TOLERANCES:" at 289.769,142.682 h1.52
  text "METAL" at 320.243,142.682 h1.52
  text "5" at 334.879,142.683 h1.52
  text "3" at 356.037,142.683 h1.52
  text "MIL" at 358.99,142.682 h1.52
  text "HOLE SIZE TOLERANCE (UNLESS OTHERWISE SPECIFIED):" at 289.769,140.185 h1.52
  text "+/-" at 349.961,140.112 h1.52
  text "3" at 356.037,140.085 h1.52
  text "MIL" at 358.99,140.085 h1.52
  text "MATERIAL:" at 287.87,136.589 h1.52
  text "FR-4 High Tg" at 312.926,133.324 h1.52
  text "X" at 309.257,133.122 h1.52
  text "FR-4" at 298.563,133.007 h1.52
  text "OTHER" at 336.358,133.007 h1.52
  text "62 MIL (1.6mm) +/-10%" at 306.694,129.374 h1.52
  text "X" at 303.643,129.312 h1.52
  text "THICKNESS:" at 289.769,129.165 h1.52
  text "OTHER" at 339.33,129.165 h1.52
  text "TOLERANCE:" at 289.769,125.652 h1.52
  text "X" at 311.314,125.652 h1.52
  text "ANSI IPC-6012 TYPE 3 CLASS 2" at 315.836,125.652 h1.52
  text "OTHER +/-" at 315.835,121.989 h1.52
  text "BOW & TWIST:" at 289.769,118.302 h1.52
  text "X" at 311.314,118.302 h1.52
  text "ANSI IPC-6012 TYPE 3 CLASS 2" at 315.836,118.302 h1.52
  text "OTHER +/-" at 315.835,114.576 h1.52
  text "DRILLING:" at 287.87,111.258 h1.52
  text "NC_DRILL FILES" at 332.599,108.586 h1.52
  text "REFERENCE:" at 289.769,108.486 h1.52
  text "X" at 306.463,108.484 h1.52
  text "AS SHOWN" at 310.984,108.486 h1.52
  text "X" at 329.348,108.486 h1.52
  text "OTHER" at 340.168,104.873 h1.52
  text "PTH COPPER THICKNESS:" at 289.761,104.783 h1.52
  text "X" at 318.697,104.783 h1.52
  text "20-30 um" at 321.948,104.783 h1.52
  text "BOARD FINISH:" at 287.87,101.034 h1.52
  text "SILKSCREEN:" at 291.812,98.237 h1.52
  text "X" at 316.14,98.237 h1.52
  text "TOP" at 319.112,98.237 h1.52
  text "X" at 329.094,98.237 h1.52
  text "BOTTOM" at 332.091,98.237 h1.52
  text "SILKSCREEN COLOR:" at 291.812,94.295 h1.52
  text "X" at 316.115,94.295 h1.52
  text "WHITE" at 319.112,94.295 h1.52
  text "OTHER" at 332.091,94.295 h1.52
  text "X" at 319.442,90.652 h1.52
  text "GREEN" at 322.439,90.652 h1.52
  text "OTHER" at 338.136,90.652 h1.52
  text "SOLDER RESIST COLOR:" at 291.812,90.477 h1.52
  text "X" at 319.442,86.734 h1.52
  text "MATTE" at 322.439,86.734 h1.52
  text "SEMI-GLOSS" at 338.125,86.717 h1.52
  text "IMMERSION GOLD (ENIG)" at 314.819,82.345 h1.52
  text "ENEPIG" at 348.793,82.162 h1.52
  text "SURFACE FINISH:" at 287.87,82.136 h1.52
  text "X" at 310.298,82.136 h1.52
  text "IMM. TIN/SILVER OR EQUIV" at 296.24,78.649 h1.52
  text "OTHER" at 332.599,78.549 h1.52
  text "ARRAY/PANEL:" at 287.87,74.602 h1.52
  text "CUT AND TRIM PER M1 BOARD OUTLINE" at 314.819,74.393 h1.52
  text "N.C. ROUTE" at 314.819,70.94 h1.52
  text "X" at 332.295,70.94 h1.52
  text "V. SCORE" at 336.816,70.94 h1.52
  text "CERTIFICATION:" at 287.87,67.66 h1.52
  text "MATERIALS AND WORKMANSHIP FOR ALL PCBS" at 306.285,67.66 h1.52
  text "TO MEET OR EXCEED THE REQUIREMENTS OF:" at 306.285,65.271 h1.52
  text "X" at 297.078,62.003 h1.52
  text "ANSI IPC-A-600F CLASS ->" at 300.329,62.003 h1.52
  text "X" at 342.188,62.003 h1.52
  text "2" at 344.982,62.003 h1.52
  text "1" at 336.981,61.965 h1.52
  text "3" at 353.973,61.965 h1.52
  text "X" at 317.702,58.252 h1.52
  text "RoHS" at 320.953,58.252 h1.52
  text "OTHER" at 337.321,58.252 h1.52
  text "PER ORDER" at 347.407,58.252 h1.52
  text "ALL BOARDS MUST MEET OR EXCEED UL94-V0 REQUIREMENTS." at 288.569,54.345 h1.52
  text "PCB MUST BEAR THE UL94V-0 UL REGISTERED MATERIAL ID NUMBER" at 288.569,51.397 h1.52
  text "ADDITIONAL REQUIREMENTS:" at 287.87,47.094 h1.52
  text "MICROSECTION:" at 289.769,44.373 h1.52
  text "YES" at 312.775,44.373 h1.52
  text "REQUIRED" at 334.657,40.707 h1.52
  text "BARE BOARD ELEC. TEST:" at 289.769,40.634 h1.52
  text "NONE" at 322.935,40.634 h1.52
  text "X" at 331.66,40.634 h1.52
  text "PER ORDER" at 349.693,40.634 h1.52
  text "XX MIL VIAS REQUIRE NON-CONDUCTIVE FILL AND PLANARIZE" at 294.04,35.428 h1.5
  text "XX MIL VIAS REQUIRE CONDUCTIVE FILL AND PLANARIZE" at 294.243,32.787 h1.52
  text "OUTER XX MIL TRACES REQUIRE 50 OHM SINGLE-ENDED IMPEDANCE" at 294.218,28.637 h1.47
  text "LAYER 2 & 3 (INNER LAYERS) XX MIL WIDE, XX MIL SPACE / TRACES REQUIRE 100 OHM DIFFERENTIAL IMPEDANCE" at 294.015,22.65 h1.52
  text ".Layer_Name" at 14.656,-21.806 h1.52
M11 Gerber Information:
  lines w0.254: -7.417,-23.626 160.223,-23.626 ; -7.417,-18.462 160.274,-18.462 ; -7.417,-13.297 -7.417,-28.791 94.31,-28.791 160.274,-28.791 160.274,-13.297 -7.404,-13.297 -7.404,-28.791 32.614,-28.791 ; 55.194,-28.791 55.194,-13.297 ; 87.376,-18.462 87.376,-13.297 ; 108.712,-18.462 108.712,-13.297 ; 124.511,-28.956 124.511,-23.804
  text "ALL ARTWORK VIEWED FROM TOP SIDE" at -5.804,-16.654 h1.52
  text "BOARD #:" at 57.099,-16.654 h1.52
  text ".PRJ_Number" at 70.955,-16.654 h1.52
  text "REV:" at 92.405,-16.654 h1.52
  text ".PCB_Rev" at 99.809,-16.654 h1.52
  text "SVN REV:" at 113.69,-16.654 h1.52
  text ".VersionControl_RevNumber" at 126.543,-16.654 h1.52
  text "LAYER NAME =" at -5.804,-21.806 h1.52
  text "TID #:" at 57.099,-21.819 h1.52
  text ".TID" at 70.955,-21.819 h1.52
  text "PLOT NAME =" at -5.804,-27.034 h1.52
  text ".plot_File_Name" at 14.656,-27.034 h1.52
  text "GENERATED    :" at 57.15,-27.034 h1.52
  text ".Print_Date" at 79.235,-27.034 h1.52
  text ".Print_Time" at 97.752,-27.034 h1.52
  text "TEXAS INSTRUMENTS" at 129.87,-27.034 h1.52
M12 Stackup:
  drawing of 399 lines, arcs and shapes, not listed
  text "Layer" at 249.469,200.023 h1.52
  text "Name" at 259.88,200.023 h1.52
  text "Material" at 283.496,200.023 h1.52
  text "Thickness" at 305.334,200.023 h1.52
  text "Constant" at 321.84,200.023 h1.52
  text "Board Layer Stack" at 336.314,200.023 h1.52
  text "Top Overlay" at 259.88,196.975 h1.52
  text "Top Solder" at 259.88,193.927 h1.52
  text "Solder Resist" at 283.496,193.927 h1.52
  text "0.40mil" at 305.334,193.927 h1.52
  text "3.5" at 321.84,193.927 h1.52
  text "1" at 249.469,190.879 h1.52
  text "Top Layer" at 259.88,190.879 h1.52
  text "2.80mil" at 305.334,190.879 h1.52
  text "Dielectric 1" at 259.88,187.831 h1.52
  text "PP-006" at 283.496,187.831 h1.52
  text "7.00mil" at 305.334,187.831 h1.52
  text "4.1" at 321.84,187.831 h1.52
  text "2" at 249.469,184.783 h1.52
  text "Layer 1" at 259.88,184.783 h1.52
  text "CF-004" at 283.496,184.783 h1.52
  text "2.80mil" at 305.334,184.783 h1.52
  text "Dielectric 5" at 259.88,181.735 h1.52
  text "Core-009" at 283.496,181.735 h1.52
  text "14.00mil" at 305.334,181.735 h1.52
  text "4.5" at 321.84,181.735 h1.52
  text "3" at 249.469,178.687 h1.52
  text "Layer 3" at 259.88,178.687 h1.52
  text "CF-004" at 283.496,178.687 h1.52
  text "2.80mil" at 305.334,178.687 h1.52
  text "Dielectric1" at 259.88,175.639 h1.52
  text "FR-4 High Tg" at 283.496,175.639 h1.52
  text "7.00mil" at 305.334,175.639 h1.52
  text "4.8" at 321.84,175.639 h1.52
  text "4" at 249.469,172.591 h1.52
  text "Layer 4" at 259.88,172.591 h1.52
  text "CF-004" at 283.496,172.591 h1.52
  text "2.80mil" at 305.334,172.591 h1.52
  text "Dielectric 6" at 259.88,169.543 h1.52
  text "Core-009" at 283.496,169.543 h1.52
  text "14.00mil" at 305.334,169.543 h1.52
  text "4.5" at 321.84,169.543 h1.52
  text "5" at 249.469,166.495 h1.52
  text "Layer 2" at 259.88,166.495 h1.52
  text "CF-004" at 283.496,166.495 h1.52
  text "2.80mil" at 305.334,166.495 h1.52
  text "Dielectric 2" at 259.88,163.447 h1.52
  text "PP-006" at 283.496,163.447 h1.52
  text "7.00mil" at 305.334,163.447 h1.52
  text "4.1" at 321.84,163.447 h1.52
  text "6" at 249.469,160.399 h1.52
  text "Bottom Layer" at 259.88,160.399 h1.52
  text "2.80mil" at 305.334,160.399 h1.52
  text "Bottom Solder" at 259.88,157.351 h1.52
  text "Solder Resist" at 283.496,157.351 h1.52
  text "0.40mil" at 305.334,157.351 h1.52
  text "3.5" at 321.84,157.351 h1.52
  text "Bottom Overlay" at 259.88,154.303 h1.52
  text ".Layer_Name" at 14.656,-21.806 h1.52
M13 Component Bodies Top:
  text ".Layer_Name" at 14.656,-21.806 h1.52
M14 Component Bodies Bottom:
  text ".Layer_Name" at 14.656,-21.806 h1.52
M15 Courtyards Top:
  text ".Layer_Name" at 14.656,-21.806 h1.52
M16 Courtyards Bottom:
  text ".Layer_Name" at 14.656,-21.806 h1.52
Drill Drawing:
  circle w0.254: c136.238,80.415 r0.702
  lines w0.254: 135.537,77.959 136.94,77.959 136.238,76.556 135.537,77.959 ; 135.537,82.871 136.94,82.871 136.94,84.275 135.537,84.275 135.537,82.871
  lines w0.305: 134.264,75.609 216.344,75.609 ; 134.264,85.082 216.344,85.082 ; 142.846,72.451 142.846,88.24 ; 151.279,72.451 151.279,88.24 ; 167.448,72.451 167.448,88.24 ; 174.03,72.451 174.03,88.24 ; 183.559,72.451 183.559,88.24 ; 201.957,72.451 201.957,88.24 ; 134.264,72.451 216.344,72.451 216.344,88.24 134.264,88.24 134.264,72.451
  text "Symbol" at 136.159,86.029 h1.83
  text "Quantity" at 143.793,86.029 h1.83
  text "Finished Hole Size" at 152.226,86.029 h1.83
  text "Plated" at 168.395,86.029 h1.83
  text "Hole Type" at 174.977,86.029 h1.83
  text "Drill Layer Pair" at 184.506,86.029 h1.83
  text "Hole Tolerance" at 202.904,86.029 h1.83
  text "2" at 143.793,82.871 h1.52
  text "214.57mil (5.450mm)" at 152.226,82.871 h1.52
  text "PTH" at 168.395,82.871 h1.52
  text "Round" at 174.977,82.871 h1.52
  text "Top Layer - Bottom Layer" at 184.506,82.871 h1.52
  text "2" at 143.793,79.714 h1.52
  text "118.11mil (3.000mm)" at 152.226,79.714 h1.52
  text "PTH" at 168.395,79.714 h1.52
  text "Rectangle" at 174.977,79.714 h1.52
  text "Top Layer - Bottom Layer" at 184.506,79.714 h1.52
  text "12" at 143.793,76.556 h1.52
  text "51.18mil (1.300mm)" at 152.226,76.556 h1.52
  text "PTH" at 168.395,76.556 h1.52
  text "Slot" at 174.977,76.556 h1.52
  text "Top Layer - Bottom Layer" at 184.506,76.556 h1.52
  text "16 Total" at 143.793,73.398 h1.52
  text "Slot definitions :" at 136.159,71.188 h1.52
  text "Routed Path Length" at 147.607,71.188 h1.52
  text "= Calculated from tool start centre position to tool end centre position." at 161.317,71.188 h1.52
  text "Hole Length" at 147.607,69.925 h1.52
  text "= Routed Path Length + Tool Size = Slot length as defined in the PCB layout" at 156.242,69.925 h1.52
  text ".Layer_Name" at 14.656,-21.806 h1.52
M17 Embedded Cavity:
  text ".Layer_Name" at 14.656,-21.806 h1.52
M18 Embedded Assembly:
  text ".Layer_Name" at 14.656,-21.806 h1.52
M19 Embedded Keepout:
  text ".Layer_Name" at 14.656,-21.806 h1.52

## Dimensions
0,-10.16 to 25.4,-10.16 on M2 Board Dimensions
0,0 to 0,43 on M2 Board Dimensions
0,0 to 4.572,14.91 on M2 Board Dimensions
